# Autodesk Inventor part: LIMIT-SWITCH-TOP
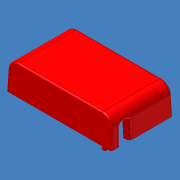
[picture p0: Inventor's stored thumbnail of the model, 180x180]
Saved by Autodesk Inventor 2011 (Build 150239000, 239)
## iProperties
Created: 2007-08
Part Number: LIMIT-SWITCH-TOP
Material: ABS Plastic
Document SubType Name: Modeling
Density: 1.06 g/cm^3
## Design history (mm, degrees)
feature "Base1"
body "Solid1"
